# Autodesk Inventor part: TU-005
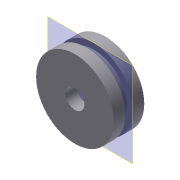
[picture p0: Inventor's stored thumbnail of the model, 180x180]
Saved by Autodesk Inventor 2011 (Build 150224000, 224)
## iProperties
Created: 2008-06
Part Number: TU-005
Document SubType Name: Modeling
Designer: PN
Density: 2.71 g/cm^3
Material: Aluminum-6061
Description: Piston
Mass: 37.162 g
Surface Area: 61.5099 cm^2
Volume: 13.7129 cm^3
Author: PN
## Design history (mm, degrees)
sketch "Sketch1"
  geometry: L1 (5, 0)-(5, 6); L2 (5, 6)-(13, 6); L3 (13, 6)-(13, 16); L4 (17.4, 10)-(17.4, 6); L5 (13, 16)-(20.4, 16); L6 (20.4, 16)-(20.4, 10); L7 (20.4, 10)-(17.4, 10); L8 (17.4, 6)-(20.4, 6); L9 (20.4, 6)-(20.4, 0); L10 (20.4, 0)-(5, 0); L11 (0, 0)-(0, 16)
  constraints: 22 end point, 2 collinear, 2 horizontal alignment, 1 horizontal, 1 perpendicular
  dimensions: "d0" = 10 diameter of L1 L11; "d1" = 26 diameter of L3 L11; "d3" = 40.8 diameter of L9 L11; "d4" = 6 distance between parallel lines of L8 L10; "d5" = 10 distance between parallel lines of L7 L10; "d6" = 16 distance between parallel lines of L5 L10; "d8" = 3 distance between parallel lines of L9 L4
revolve "Revolution1" sketch "Sketch1" stored, may be unused: angle "d7" = 90 deg
workplane "Work Plane1"
body "Solid1"
other parameters: "d9" = 8
